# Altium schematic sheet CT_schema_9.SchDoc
size 254 x 194 mm
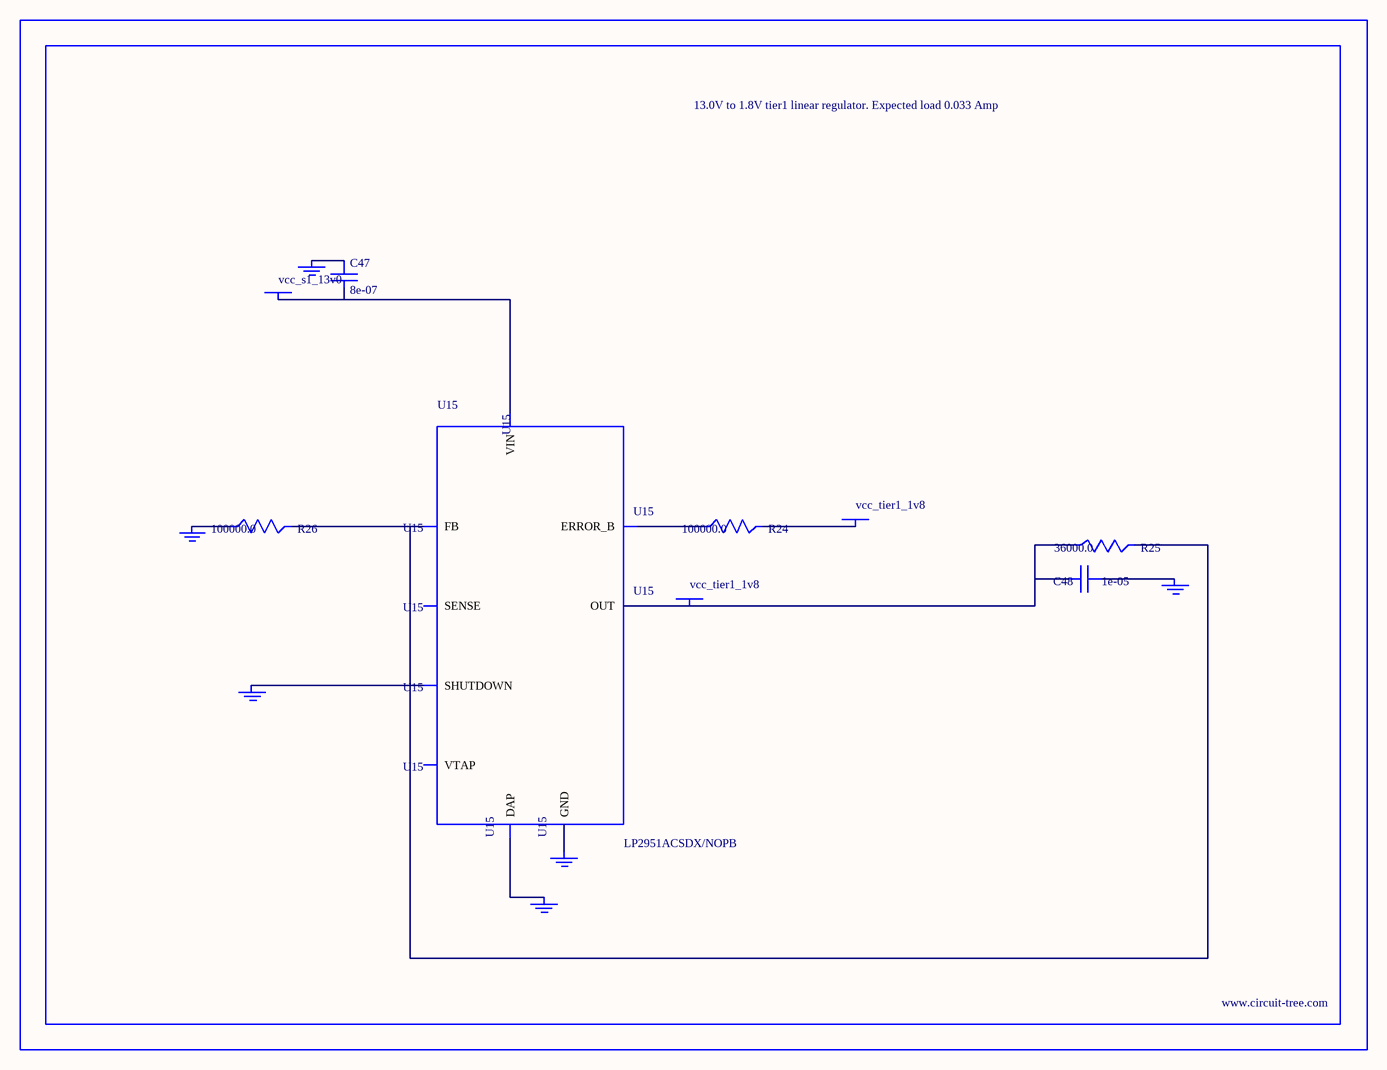
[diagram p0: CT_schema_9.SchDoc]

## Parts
BORDER8  (no value)
C47  8e-07  [R0603]
C48  1e-05  [C0805]
GND_INSTANCE_8_0  (no value)
GND_INSTANCE_8_1  (no value)
GND_INSTANCE_8_2  (no value)
GND_INSTANCE_8_3  (no value)
GND_INSTANCE_8_4  (no value)
GND_INSTANCE_8_5  (no value)
POWER_INSTANCE_8_0  vcc_tier1_1v8
POWER_INSTANCE_8_1  vcc_s1_13v0
POWER_INSTANCE_8_2  vcc_tier1_1v8
R24  100000.0  [R0603]
R25  36000.0  [R0603]
R26  100000.0  [R0603]
U15  LP2951ACSDX/NOPB  [WSON-8]

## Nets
NetC47_1: C47.1 GND_INSTANCE_8_3.0(GND)
NetC47_2: C47.2 POWER_INSTANCE_8_1.0(PWR) U15.8(VIN)
NetC48_1: C48.1 GND_INSTANCE_8_0.0(GND)
NetC48_2: C48.2 POWER_INSTANCE_8_2.0(PWR) R25.1 U15.1(OUT)
NetGND_INSTANCE_8_1_0: GND_INSTANCE_8_1.0(GND) U15.3(SHUTDOWN)
NetGND_INSTANCE_8_2_0: GND_INSTANCE_8_2.0(GND) R26.1
NetGND_INSTANCE_8_4_0: GND_INSTANCE_8_4.0(GND) U15.PAD(DAP)
NetGND_INSTANCE_8_5_0: GND_INSTANCE_8_5.0(GND) U15.4(GND)
NetPOWER_INSTANCE_8_0_0: POWER_INSTANCE_8_0.0(PWR) R24.2
NetR24_1: R24.1 U15.5(ERROR_B)
NetR25_2: R25.2 R26.2 U15.7(FB)

Not connected (* = marked no-connect by the designer): U15 2(SENSE) 6(VTAP)

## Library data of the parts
BORDER8 = BORDER_PAGE8
C47 = C47
C48 = GRM219R60J106ME19D
GND_INSTANCE_8_0-GND_INSTANCE_8_5 = GND
POWER_INSTANCE_8_0-POWER_INSTANCE_8_2 = PWR
R24 R26 = RC0603JR-07100KL
R25 = RC0603JR-0736KL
